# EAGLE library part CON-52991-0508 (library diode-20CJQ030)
Molex 52991-0508 50pin Board to Board connector with a pitch 0.5 mm
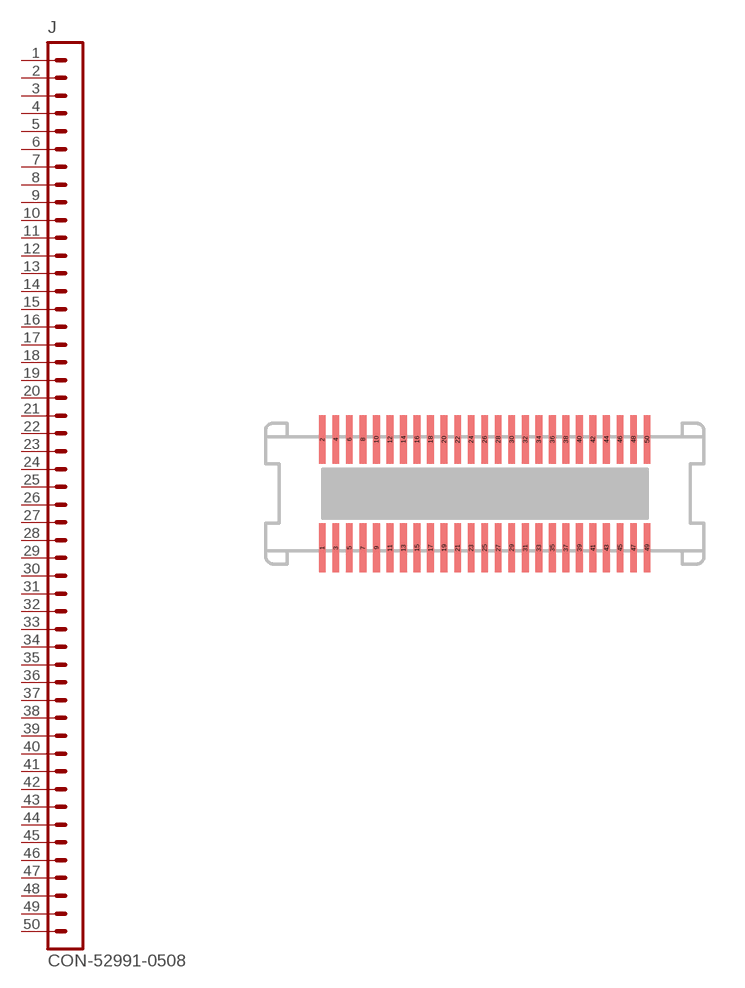
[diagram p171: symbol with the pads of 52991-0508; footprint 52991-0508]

Designator prefix J

## CON-52991-0508  [52991-0508]
1  1  pas
2  2  pas
3  3  pas
4  4  pas
5  5  pas
6  6  pas
7  7  pas
8  8  pas
9  9  pas
10  10  pas
11  11  pas
12  12  pas
13  13  pas
14  14  pas
15  15  pas
16  16  pas
17  17  pas
18  18  pas
19  19  pas
20  20  pas
21  21  pas
22  22  pas
23  23  pas
24  24  pas
25  25  pas
26  26  pas
27  27  pas
28  28  pas
29  29  pas
30  30  pas
31  31  pas
32  32  pas
33  33  pas
34  34  pas
35  35  pas
36  36  pas
37  37  pas
38  38  pas
39  39  pas
40  40  pas
41  41  pas
42  42  pas
43  43  pas
44  44  pas
45  45  pas
46  46  pas
47  47  pas
48  48  pas
49  49  pas
50  50  pas

## Footprint 52991-0508 (pad centres in mm)
Molex board to board connector
smd 0.25 x 1.8: 1 -6,-2; 2 -6,2; 3 -5.5,-2; 4 -5.5,2; 5 -5,-2; 6 -5,2; 7 -4.5,-2; 8 -4.5,2; 9 -4,-2; 10 -4,2; 11 -3.5,-2; 12 -3.5,2; 13 -3,-2; 14 -3,2; 15 -2.5,-2; 16 -2.5,2; 17 -2,-2; 18 -2,2; 19 -1.5,-2; 20 -1.5,2; 21 -1,-2; 22 -1,2; 23 -0.5,-2; 24 -0.5,2; 25 0,-2; 26 0,2; 27 0.5,-2; 28 0.5,2; 29 1,-2; 30 1,2; 31 1.5,-2; 32 1.5,2; 33 2,-2; 34 2,2; 35 2.5,-2; 36 2.5,2; 37 3,-2; 38 3,2; 39 3.5,-2; 40 3.5,2; 41 4,-2; 42 4,2; 43 4.5,-2; 44 4.5,2; 45 5,-2; 46 5,2; 47 5.5,-2; 48 5.5,2; 49 6,-2; 50 6,2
